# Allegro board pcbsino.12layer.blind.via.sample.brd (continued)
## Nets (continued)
VSYS_5V0: C1.2 C4.1 C6.1 C18.1 C21.1 C23.1 C25.1 C27.1 C32.1 C33.1 C37.1 C38.1 C42.1 C45.1 C46.2 C48.2 C50.2 C52.1 R4.2 R8.2(P2) R9.1 R23.1 R27.1 R44.1 R45.1 R48.2 R227.1 R228.1 R229.1 TP1.1 U1.5(SENSE) U1.6(VDD) U3.A6(LDO12_IN) U3.C4(LDO9_IN) U3.C5(LDOLN_IN) U3.C7(VCC1) U3.D11(SMPS1_IN_1) U3.D12(SMPS1_IN_2) U3.D13(SMPS1_IN_3) U3.E1(SMPS7_IN_B1_1) U3.E2(SMPS7_IN_B1_2) U3.E3(SMPS7_IN_B1_3) U3.F1(SMPS4_IN_1) U3.F2(SMPS4_IN_2) U3.F3(SMPS4_IN_3) U3.G11(SMPS2_IN_1) U3.G12(SMPS2_IN_2) U3.G13(SMPS2_IN_3) U3.H11(SMPS3_IN_1) U3.H12(SMPS3_IN_2) U3.H13(SMPS3_IN_3) U3.J1(SMPS5_IN_1) U3.J2(SMPS5_IN_2) U3.J3(SMPS5_IN_3) U3.L12(LDO34_IN) U3.L13(LDO34_IN_1) U3.M4(NC6) U3.M6(SMPS6_IN) U3.M8(SMPS9_IN) U3.M9(SMPS8_IN) U3.N3(NC7) U3.N4(NC8) U3.N6(SMPS6_IN_1) U3.N8(SMPS9_IN_1) U3.N9(SMPS8_IN_1) U4.5(VCC) XP1.10(VSYS13) XP1.28(VSYS14) XP1.46(VSYS15) XP1.64(VSYS16) XP1.78(VSYS) XP1.96(VSYS1) XP1.114(VSYS2) XP1.132(VSYS3) XP1.150(VSYS4) XP1.168(VSYS5) XP1.186(VSYS6) XP1.204(VSYS7)
VTT_DDR: C9.1 C10.1 C11.1 C66.1 C67.1 C68.1 C69.1 C70.1 C71.1 C72.1 C103.1 C104.1 C105.1 C106.1 C107.1 C108.1 C109.1 R15.1(P1) R68.1(P1) R69.1(P1) R70.1(P1) R71.1(P1) R72.1(P1) R73.1(P1) R74.1(P1) R75.1(P1) R76.1(P1) R77.1(P1) R78.1(P1) R79.1(P1) R80.1(P1) R81.1(P1) R82.1(P1) R83.1(P1) R84.1(P1) R85.1(P1) R86.1(P1) R87.1(P1) R88.1(P1) R89.1(P1) R90.1(P1) R91.1(P1) R92.1(P1) R101.1(P1) R102.1(P1) R103.1(P1) R104.1(P1) R105.1(P1) R106.1(P1) R107.1(P1) R108.1(P1) R109.1(P1) R110.1(P1) R111.1(P1) R112.1(P1) R113.1(P1) R114.1(P1) R115.1(P1) R116.1(P1) R117.1(P1) R118.1(P1) R119.1(P1) R120.1(P1) R121.1(P1) R122.1(P1) R123.1(P1) R124.1(P1) R125.1(P1) TP2.1 U2.3(VTT)
VUSB_3V3: C31.2 C160.1 C161.1 C162.1 TP17.1 U3.B9(LDOUSB_OUT) U6.AA12(VDDA33V_USB1) U6.Y12(VDDA33V_USB2)
N05979: R320.2 R321.2 XP1.200(USB1_DRVVBUS;GPIO6_12;TIMER16)
N17551517: R45.2 U3.B3(VCC_SENSE)
N17551519: R44.2 U3.A11(VCC_SENSE2)
N17551928: C17.2 U3.B7(VBG)
N25853972: R31.1 R32.1 U3.K7(BOOT1)
N28613451: R22.2 R25.2 U3.E6(NRESWARM)
N28614012: R19.2 R24.2 R26.2 U3.E5(NSLEEP)
N28708877: C15.1 U3.A2(OSC16MOUT) Y1.1
N29245750: R63.2 R64.1 U6.AE14(RTC_OSC_XI_CLKIN32)
N29975844: C16.1 U3.C1(OSC16MCAP)
N31526000: L13.1 U17.32(REGOUT)
N31599735: L19.1 U19.32(REGOUT)
N31726154: C145.1 C146.2 U12.C2(VDDIM)
N32045954: C73.1 R93.1(P1) R94.1(P1)
N32303458: C110.1 R126.1(P1) R127.1(P1)
N32341441: D2.1(REF) R5.1 R10.2 R16.2
N32341443: D2.2(CATHODE) Q1.1(BASE) R1.1 R10.1
N32341445: D3.1(REF) R6.1 R12.2 R17.2
N32341447: D3.2(CATHODE) Q2.1(BASE) R3.1 R12.1
N32350953: C319.2 U6.Y15(CAP_VDDRAM_CORE3)
N32350956: C320.1 U6.R20(CAP_VBBLDO_IVA)
N32350987: C321.2 U6.J19(CAP_VDDRAM_CORE2)
N32350990: C322.1 U6.Y14(CAP_VBBLDO_GPU)
N32351019: C323.2 U6.P19(CAP_VDDRAM_CORE4)
N32351022: C324.1 U6.J16(CAP_VBBLDO_MPU)
N32351049: C325.2 U6.Y16(CAP_VDDRAM_CORE5)
N32351052: C326.1 U6.J10(CAP_VDDRAM_DSP)
N32351083: C327.2 U6.K9(CAP_VBBLDO_DSP)
N32351086: C328.1 U6.T20(CAP_VDDRAM_IVA)
N32351113: C329.2 U6.J9(CAP_VDDRAM_DSP2)
N32351116: C330.1 U6.Y13(CAP_VDDRAM_GPU)
N32351145: C331.2 U6.K19(CAP_VDDRAM_MPU2)
N32351151: C332.1 R318.1 U6.K16(CAP_VDDRAM_MPU1)
N32351171: C333.2 U6.L9(CAP_VDDRAM_CORE1)
N32388958: R319.1 XP1.183(BACKUP_BAT)
N32392766: R230.1 R234.2 U16.7(WP)
N32392999: R164.1 R168.2 R170.2
N32637123: C35.2 U3.C8(LDOVANA_OUT)
N32670742: C14.1 R18.2 U3.A3(OSC16MIN) Y1.3
N32674796: TP4.1 U3.M11(CLK32KGO)
N32678230: R35.2 U3.B12(GPIO_0)
N32680788: R40.2 U3.C10(GPIO_5/CLK32KGO)
N32681411: R37.2 U3.A12(GPIO_2/REGEN2)
N32684937: R36.2 U3.C13(GPIO_1/VBUSDET)
N32685500: R46.1 R47.1(P1) U3.D8(VBUS)
N32689068: R41.2 R43.1 U3.G9(GPIO_7/POWERHOLD)
N32690150: R38.2 U3.H9(GPIO_3)
N32694377: R29.1 R30.1 U3.L3(BOOT0)
N32708016: TP6.1 U3.C11(RPWRON)
N32708264: TP9.1 U3.K8(PWRDOWN)
N32708462: TP10.1 U3.N12(VPROG/TESTV)
N32708995: R39.2 U3.K10(GPIO_4/SYSEN1)
N32710130: R34.1 R36.1 U4.2(A)
N32710609: R42.2 U3.N11(GPIO_6/SYSEN2)
N32734224: C34.1 R48.1 R50.2 U3.A9(LDOUSB_IN2) U3.A10(LDO7USB_IN1)
N32811364: C7.1 R8.1(P1) U1.4(CT)
N32826883: D1.2(A) R9.2
N32827036: TP7.1 U3.F8(REGEN1)
N32966375: C5.1 R2.2 R7.2 U2.1(VRI)
N32966437: R13.1 R14.1(P1) U2.7(EN)
N32966504: C13.1 R15.2(P2) U2.5(VTTS)
N32992437: R172.1 U6.A17(MCASP2_AXR7)
N33004530: R60.1 U6.AB16(WAKEUP2)
N33116208: R56.1 U6.D21(NMIN)
N33266046: Q8.D(DRAIN) R327.1 R329.1(P1)
N33266747: Q7.D(DRAIN) R323.1 R324.1(P1)
N261608581: R99.2 U6.V27(DDR1_DQS_ECC)
N261608661: R100.2 U6.V28(DDR1_DQSN_ECC)
N323928681: R160.2 U13.10(NC.10)
N323929221: R162.2 U13.8(NC.8)
N329663413: R11.2 U2.9(PGOOD)
N330092162: D4.1(C) Q3.D(DRAIN)
N330103841: D4.2(A) R23.2
N330155391: D5.2(A) R227.2
N330155500: D5.1(C) Q4.D(DRAIN)
N330160361: D6.2(A) R228.2
N330160440: D6.1(C) Q5.D(DRAIN)
N330162891: D7.2(A) R229.2
N330162970: D7.1(C) Q6.D(DRAIN)
N330247804: R161.2 U14.5(DIR)
N330247805: R163.2 U14.4(B)
N3195997380: R97.1 U9.L8(ZQ)
N3196008080: R96.1 U8.L8(ZQ)
N3196802080: R129.1 U10.L8(ZQ)
N3196813480: R130.1 U11.L8(ZQ)

Pads without a net: NOREF 1; NOREF#3 1; NOREF#5 1; NOREF#7 1; NOREF#8 1; NOREF#9 1; P1 6 17 18 19; U3 B4 C9 K4 K5 L4; U4 1; U6 A13 A16 A20 A26 A27 AA1 AA2 AB1 AB2 AC1 AC2 AD3 AD8 AD9 AD14 AE1 AE2 AE3 AE5 AE6 AE8 AE9 AF1 AF2 AF3 AF4 AF6 AF8 AF9 AG2 AG3 AG4 AG5 AG6 AG7 AG8 AH3 AH4 AH5 AH6 AH7 B22 B28 C1 C15 D1 D2 D3 E1 E2 E4 E6 E14 E15 F2 F3 F4 F5 F6 F14 G1 G14 G17 H7 K14 M3 M4 M5 N1 N2 N6 N7 N9 P1 P5 P6 P7 P9 R4 R5 R6 R9 T6 T7 T9 V23 V24 V25 V26 W19 W22 W23 Y5 Y10 Y25 Y26; U7 1; U8 J1 J9 L1 L9; U9 J1 J9 L1 L9; U10 J1 J9 L1 L9; U11 J1 J9 L1 L9; U12 A1 A2 A7 A8 A9 A10 A11 A12 A13 A14 B1 B7 B8 B9 B10 B11 B12 B13 B14 C1 C3 C5 C7 C8 C9 C10 C11 C12 C13 C14 D1 D2 D3 D4 D12 D13 D14 E1 E2 E3 E5 E8 E9 E10 E12 E13 E14 F1 F2 F3 F10 F12 F13 F14 G1 G2 G3 G10 G12 G13 G14 H1 H2 H3 H5 H12 H13 H14 J1 J2 J3 J12 J13 J14 K1 K2 K3 K6 K7 K10 K12 K13 K14 L1 L2 L3 L12 L13 L14 M1 M2 M3 M7 M8 M9 M10 M11 M12 M13 M14 N1 N3 N6 N7 N8 N9 N10 N11 N12 N13 N14 P1 P2 P7 P8 P9 P10 P11 P12 P13 P14; U17 33 38 39 40 41 42 43 44; U19 33 38 39 40 41 42 43 44; XP1 2 4 33 35 39 41 45 47 51 53 57 59 107 158 160 164 166 181 191

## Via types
v1: diameter 0.254, hole 0.102, TOP to GND_L2, 857 vias
v2: diameter 0.254, hole 0.102, GND_L2 to INT_L3, 684 vias
v3: diameter 0.457, hole 0.203, INT_L3 to SIG_L10, 312 vias
v4: diameter 0.254, hole 0.102, SIG_L10 to GND_L11, 218 vias
v5: diameter 0.254, hole 0.102, GND_L11 to BOTTOM, 597 vias
v6: diameter 0.356, hole 0.203, TOP to BOTTOM, 10 vias
v7: diameter 0.457, hole 0.203, TOP to BOTTOM, 226 vias
v8: diameter 0.406, hole 0.203, TOP to BOTTOM, 665 vias

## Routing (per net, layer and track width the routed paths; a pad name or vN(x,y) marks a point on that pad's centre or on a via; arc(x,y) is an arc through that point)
GND: length 424
  TOP w0.102: v2(21.73,2.71) 21.71,2.73 C55.2 ; C11.2 15.28,59.29 15.28,59.3 v1(15.28,59.39) ; R274.1 49.98,26.45 v2(50.26,26.45) ; v2(28.03,6.51) 28.03,6.51 28.03,6.62 U12.H10 ; v2(29.56,9.87) 29.91,9.51 30.19,9.51 30.54,9.86 U12.C4 ; C13.2 15.13,62.8 15.21,62.88 v2(15.21,62.99) ; C24.2 19.18,46.51 v1(18.46,47.23) ; C137.2 v1(17.83,18.39) ; U12.A6 v1(31.89,8.91)
  TOP w0.114: U3.G5 30.74,57.81 ; U6.W28 v8(19.07,32.77) ; U6.AD24 v8(23.07,35.97) ; U3.G4 U3.F4
  TOP w0.127: C2.2 7.62,65.79 v7(7.46,65.95) ; 53.48,27.03 54.32,26.2 54.32,23.33 53.92,22.92 50.16,22.92 49.78,23.3 ; C8.1 v7(5.71,58.2)
  TOP w0.203: U3.A7 36.38,55.42 v1(36.77,55.82) 37.05,56.1 v1(37.05,56.17) ; R191.2 44.54,25.01 v1(43.2,25.01) ; v1(30.34,35.22) 30.67,35.54 U6.AC14 30.67,35.63 v1(30.32,35.98) ; U3.L10 v1(27.25,53.32) 27.25,53.53 U3.L9 ; U6.AH20 25.84,39.57 v2(25.29,40.12) ; v1(30.19,37.61) 29.87,37.93 U6.AF15 ; U6.AE13 31.09,36.79 v1(31.06,36.79) ; U3.J6 U3.H7 ; U6.AB14 30.3,34.4 v1(30.29,34.4) 30.29,34.35 U6.AA14 30.67,33.94 v1(30.27,33.54)
  TOP w0.254: U6.T18 v8(27.87,30.37) ; v8(27.87,30.37) U6.T17 ; v8(27.87,30.37) U6.U17 v8(27.87,31.17) U6.V17 v8(27.87,31.97) ; v8(41.93,25.21) 41.88,25.16 41.08,25.16 U6.K1 ; R97.2 6.64,29.52 6.64,30.92 6.95,31.23 ; v8(3.53,8.61) 3.93,9.01 U10.T9 ; U6.A2 v8(40.67,17.57) U6.A1 v8(41.47,17.57) ; U6.J12 v8(32.67,23.97) U6.H12 v8(32.67,23.17) ; 31.48,36.37 31.48,37.17 U6.AE13 ; 31.48,36.37 U6.AD13 ; 31.48,36.37 v8(31.87,35.98) ; v8(2.68,42.35) 3.67,42.35 3.93,42.61 U8.T9 ; v2(53.48,26.53) C191.2 ; U9.D8 v8(13.93,31.81) ; U9.J8 v8(9.13,31.81) ; U11.B3 v8(14.73,25.41) ; Q5.S 39.13,4.93 v2(39.13,4.61) 39.13,3.8 38.72,3.38 C155.2 ; v2(13.12,60.08) 12.91,60.3 U2.4 ; U9.B9 v8(15.53,31.01) ; U8.G8 v8(11.53,43.01) ; U6.E19 v8(26.27,20.77) U6.D19 ; R274.1 49.69,23.39 49.78,23.3 ; U11.F9 12.13,20 v8(12.33,19.81) ; v8(31.07,27.17) U6.N14 ; 6.95,31.23 7.13,31.41 ; 6.95,31.23 v8(6.73,31.01) ; U8.A9 v8(16.33,42.21) ; v8(2.73,15.84) 3.51,15.84 3.76,15.58 3.76,15.57 U10.T1 ; C156.2 9.04,4.5 v7(8.6,4.94) ; v8(19.07,27.97) U6.P28 ; U9.P1 5.53,37.81 v8(5.13,38.21) 5.04,38.3 5.04,39.75 C98.2 ; C84.1 13.38,49.66 v8(13.13,49.41) ; U8.G9 v8(11.53,42.21) ; C82.1 5.04,41.08 5.04,42.12 v8(5.13,42.21) 5.53,42.61 U8.P9 ; U5.3 22.08,6.9 v2(22.71,6.27) ; U3.M13 26.74,50.63 v7(26.36,51.02) 26.74,51.4 U3.M12 ; U6.R1 v1(41.98,29.17) ; v7(25.45,59.75) 25.78,59.42 U3.N2 25.95,59.42 v7(26.33,59.04) ; C125.1 6.98,27.6 v8(7,27.57) 7,26.73 U11.M1 ; U6.AE19 v8(26.27,36.77) U6.AD19 ; v7(26.33,59.83) 26.73,60.22 U3.M1 ; v7(26.33,59.83) U3.N1 ; v7(26.33,59.83) 26.74,59.42 U3.M2 ; U11.G1 v8(11.53,27.01) ; v7(27.93,54.24) 27.55,54.62 U3.L8 ; U3.D5 U3.D4 U3.E4 ; U11.J2 v8(9.13,26.21) ; v1(35.07,33.52) 35.07,33.57 U6.AA9 ; U10.E8 v8(13.13,9.41) ; v1(33.47,34.37) U6.AB11 32.68,35.16 v1(32.68,35.17) ; v1(33.47,34.37) U6.AA10 v8(34.27,34.37) U6.AA9 ; v1(33.47,34.37) U6.AA11 32.71,34.33 v1(32.68,34.33) ; R129.2 9.34,7.25 v7(9.64,6.95) ; U6.AH28 19.31,39.57 19.26,39.63 18.62,39.63 v8(18.57,39.68) ; U9.B1 15.13,37.81 v8(15.53,38.21) ; U11.B9 15.13,19.95 14.9,19.72 14.9,19.71 v8(14.89,19.69) 14.93,19.69 14.94,19.68 15.62,19.68 15.93,19.99 U11.A9 ; v7(35.96,60.59) 35.59,60.22 U3.A1 ; v2(55.76,27.15) 55.23,26.63 R272.1 ; R287.1 46.27,35.21 46.52,34.96 v1(46.52,34.94) ; v8(41.62,18.8) 41.58,18.8 41.56,18.77 U6.B1 ; v8(9.13,37.41) U9.J2 ; C121.1 7.13,16.94 v1(7.13,16.47) U10.M1 ; v7(32.02,53.43) 32.02,53.3 32.3,53.02 U3.E10 ; v7(32.02,53.43) 32.02,53.45 32.34,53.77 U3.E9 ; v7(32.02,53.43) 31.62,53.02 U3.F10 U3.G10 U3.F9 31.63,53.82 v7(32.02,53.43) ; U11.J8 v8(9.93,21.41) ; U3.C3 33.94,58.62 v7(34.33,59.02) 33.94,59.41 U3.C2 ; v7(36.46,58.23) 36.06,57.82 U3.A4 ; U9.M1 6.7,38.24 6.7,39.6 C89.1 ; v8(41.65,32.63) 41.47,32.63 41.22,32.37 U6.W1 ; v8(26.27,26.37) U6.M19 v1(26.27,27.17) U6.N19 ; U3.H7 29.94,55.46 v7(30.29,55.82) ; U6.T11 v8(32.67,29.57) ; U6.T11 v8(32.67,30.37) U6.T12 ; U6.T11 v8(33.47,30.37) U6.T10 ; v8(32.67,29.57) U6.R12 v8(31.87,29.57) ; v8(32.67,29.57) U6.T12 ; U11.P9 5.53,19.84 5.15,19.45 v8(5.15,19.37) 5.15,18.58 5.22,18.5 C128.1 ; U8.P1 5.53,49.01 5.53,49.75 v8(5.5,49.77) 5.26,50.01 C93.2 ; U6.R21 v1(24.67,29.57) U6.T21 v1(24.67,30.37) U6.U21 ; U6.K15 v8(29.47,24.77) U6.J15 v8(29.47,23.97) ; v8(41.9,21.97) U6.F1 ; U3.G4 30.74,57.81 v7(31.16,57.39) ; v7(32.61,55) 32.61,55.16 U3.E7 ; v7(32.61,55) 32.34,54.74 U3.E8 32.33,54.62 v7(31.92,55.03) 31.54,55.41 U3.F7 ; v7(32.61,55) 33.03,55.42 U3.D7 ; v6(34.24,36.79) 34.24,36.72 34.22,36.71 ; v8(24.67,31.17) U6.U21 ; U6.U21 v8(25.47,31.17) U6.U20 ; v8(19.43,17.41) 19.43,17.94 U6.A28 ; v8(29.47,27.17) U6.N15 ; U6.AB14 v1(31.07,34.37) U6.AA14 ; v7(31.94,55.84) 31.56,56.22 U3.F6 ; v8(11.53,38.21) 11.13,37.81 U9.G1 ; v8(2.58,19.83) 3.55,19.83 U11.T9 ; v8(31.86,21.57) U6.E13 ; v2(21.38,25.01) 21.71,25.01 21.87,25.17 ; v2(48.33,10.27) 48.33,9.75 C207.2 48.33,9.72 47.92,9.31 47.92,5.96 48.15,5.73 52.31,5.73 52.57,5.98 52.57,8.7 R301.1 52.53,8.84 v2(51.6,9.77) ; v1(46.17,36.03) 46.05,36.15 R278.1 R280.1 ; U6.AH1 40.68,39.18 v1(40.66,39.18) ; U6.AH1 v8(40.67,39.97) U6.AH2 ; U6.AH1 v8(41.47,39.17) U6.AG1 ; U6.AH1 41.13,39.57 v1(41.55,39.99) ; U12.P6 v2(24.66,8.75) ; U3.L5 27.54,57.02 v7(27.93,56.63) 27.54,56.24 U3.L6 27.55,56.22 v7(27.93,55.84) 27.54,55.45 U3.L7 ; U9.E2 12.73,37.01 v8(13.13,37.41) ; R239.1 43.69,5.18 Q6.S v2(43.71,4.69) ; v7(30.29,55.82) 29.94,56.17 U3.H6 ; v7(30.29,55.82) 30.69,55.42 U3.G7 v7(31.13,55.82) ; U9.B3 v8(15.56,35.78) ; C129.2 7.05,8.29 v8(6.73,8.61) 7.13,9.01 U10.M9 ; U3.G5 30.79,57.02 v7(31.16,57.39) ; C273.2 10.54,16.64 v8(11.32,15.86) 11.32,15.6 U10.G1 ; U10.G8 v8(11.53,9.41) ; v8(36.67,21.57) U6.F7 ; U6.F7 v8(35.87,22.37) ; U6.F7 v8(36.67,22.37) U6.G7 v8(35.87,22.37) ; U6.AA20 v8(25.47,34.37) U6.AB20 v8(25.47,35.17) ; v7(31.16,57.39) 31.54,57.77 U3.F4 ; v7(31.16,57.39) 31.17,57.39 U3.F5 ; U6.R15 v8(29.47,29.57) U6.T15 v8(29.47,30.37) U6.U15 v8(29.47,31.17) U6.V15 v8(29.47,31.97) U6.W15 ; U6.AE10 33.87,37.13 34.22,36.77 34.22,36.71 ; v8(23.39,17.16) 23.39,17.89 U6.A23 ; U6.AA8 35.88,33.57 v1(35.88,33.57) ; U6.AA8 v1(35.07,34.37) U6.AA9 ; U6.AA8 35.86,34.36 v1(35.86,34.38) ; U6.K24 22.67,25.15 v2(22.27,24.75) 21.87,25.15 21.87,25.17 ; U11.D8 13.33,20.81 v8(13.13,20.61) 12.93,20.8 U11.E8 ; U11.B1 15.37,26.85 15.37,26.85 v8(15.53,27.01) ; U10.P9 5.53,9.01 v8(5.13,8.61) 5.04,8.52 5.04,7.45 C122.1 ; v8(35.87,22.37) U6.G8 v8(35.07,22.37) U6.G9 ; C90.1 5.04,29.72 5.04,30.92 5.38,31.26 ; U6.T12 v8(31.87,29.57) ; U11.E1 12.93,26.81 12.93,26.81 v8(13.13,27.01) ; v1(9.13,43.01) 9.53,43.41 U8.J8 9.9,43.78 v1(9.9,43.83) ; v1(47.03,35.95) 46.97,36.02 R281.1 ; v7(33.57,51.8) 33.94,51.44 U3.C12 ; v8(31.87,29.57) U6.R13 ; U8.T1 3.93,49.01 3.7,49.24 v8(3.37,49.24) ; U11.M9 6.78,19.86 v8(6.78,19.37) 6.78,18.65 C124.1 ; U6.L14 v8(31.07,25.57) U6.L13 ; 3.93,31.41 v8(3.53,31.01) ; U6.K5 v8(38.27,24.77) U6.K4 v8(39.07,24.77) ; U3.B10 34.75,53.02 v7(35.14,52.64) 34.74,52.24 U3.B11 ; R303.1 46.53,8.46 v2(46.45,8.55) 46.42,8.52 46.34,8.52 R302.1 ; 34.22,36.71 33.89,36.37 U6.AD10 ; v8(15.14,16.13) 15.21,16.07 15.21,15.48 U10.B1 ; U10.B9 v8(15.53,8.61) ; v2(24.59,9.73) 24.63,9.73 24.82,9.91 U12.P4 ; U8.B3 v8(15.53,47.81) ; U10.J8 9.53,9.8 v8(9.93,9.41) ; C85.1 15.13,49.81 v8(15.53,49.41) ; v8(7.1,50.05) 7.13,50.03 7.13,49.01 U8.M1 ; U3.H10 U3.J10 U3.J9 ; v8(11.53,20.61) 11.33,20.8 U11.G8 ; v8(19.07,23.94) 19.07,23.97 U6.J28 ; v8(2.1,38.44) 3.29,38.44 3.93,37.81 U9.T1 ; U10.J2 v8(9.13,15.01) ; U10.D8 v8(13.93,9.41) ; U6.A6 37.1,17.95 v8(37.1,17.42) ; v8(11.53,31.81) U9.G8 ; U10.G9 v8(11.53,8.61) ; v1(29.47,34.37) U6.AA15 ; R237.1 41.67,5.34 Q4.S v2(41.45,4.59) ; v2(50.66,27.67) 50.63,27.64 C188.2 50.63,26.21 50.95,25.89 Y4.2 ; v8(30.93,16.89) 30.93,16.93 30.67,17.19 U6.A14 ; U3.A13 35.98,50.18 v7(36.31,50.18) ; v7(28.71,58.24) 28.68,58.24 28.34,58.59 U3.K3 ; U9.F9 v8(12.33,31.01) ; U11.D1 13.73,26.81 13.73,26.81 v8(13.93,27.01) ; v8(41.47,36.77) U6.AD1 ; U9.E8 v8(13.13,31.81) ; U8.J2 v8(9.13,48.61) ; 21.87,25.17 U6.K25 ; C133.2 5.04,17.04 5.04,15.89 5.13,15.81 v8(5.13,15.8) 5.14,15.8 U10.P1 ; v7(21.99,63.82) 22.75,63.06 v3(23.73,63.06) 23.73,62.12 v7(24.25,61.61) ; U10.D1 13.48,15.46 13.48,16.04 13.24,16.28 12.73,16.28 ; U10.B3 15,13.68 15,13.09 v8(14.95,13.04) ; v7(35.12,59.81) U3.B2 ; U11.G9 11.33,20.01 v8(11.53,19.81) ; U6.AH8 36.45,40.56 37.32,40.56 v8(37.32,40.55) ; U3.H5 U3.H4 U3.J4 ; U11.T1 3.83,26.71 3.12,26.71 v8(3.01,26.61) ; U8.E8 v8(13.13,43.01) ; U9.D1 13.53,37.89 v7(13.17,38.24) 12.74,37.81 U9.E1 ; U6.N24 v8(22.27,27.17) U6.N25 ; 5.38,31.26 v8(5.13,31.01) ; 5.38,31.26 5.53,31.41 ; v8(21.47,32.77) U6.W25 v8(22.27,32.77) U6.W24 ; 12.73,16.28 U10.E1 ; 12.73,16.28 v8(12.16,16.85) ; U8.F9 v8(12.33,42.21) ; v7(33.55,55.82) U3.D6 ; U10.F9 v8(12.33,8.61) ; v7(33.47,53.35) U3.D10 ; U6.U14 v8(31.07,30.37) U6.T14 ; U6.D13 v8(31.86,20.77) ; U8.E2 v8(13.13,48.61) ; U8.M9 7.13,42.1 v8(6.8,41.77) 6.8,41.15 C94.2 ; C134.2 5.02,28.14 5.02,28.03 4.92,27.94 v8(4.92,27.32) 5.53,26.71 U11.P1 ; U9.G9 v8(11.53,31.01) ; U10.A9 v8(16.33,8.61)
  TOP w0.381: C81.1 7.13,50.85 7.13,50.08 v8(7.1,50.05) ; v7(27.93,54.24) 27.93,54.22 U3.L9 ; U10.E2 v8(12.33,15.01) ; U2.8 v7(12.41,64.51) ; XP1.71 56.91,23.18 v7(56.46,23.64) ; XP1.1 v7(56.97,2.18) ; 7.13,31.41 U9.M9 ; C54.2 v2(16.83,6.79) ; U9.A9 v8(15.53,31.01) ; C12.2 14.77,66.19 14.77,66.76 v7(14.72,66.82) ; R130.2 6.95,18.48 C124.1 ; v2(24.66,49.82) 24.39,50.08 R42.1 ; v2(48.43,19.47) 48.24,19.28 C214.2 ; C234.2 C237.2 16.35,66.43 v7(15.84,66.94) ; U9.T9 3.93,31.41 ; v2(56.74,13.25) 57,12.98 XP1.37 ; C127.1 13.56,27.37 v8(13.93,27.01) ; U8.B9 v8(15.13,41.82) ; U11.D1 13.53,26.61 U11.E2 ; U8.D8 v8(13.13,43.01) ; v8(13.13,49.41) U8.E1 ; C76.2 11.72,49.6 v8(11.53,49.41) 11.13,49.01 U8.G1 ; v1(36.59,6.69) 36.59,6.7 v1(36.59,7.38) ; C101.2 15.47,38.27 v8(15.53,38.21) ; U3.N13 25.92,50.61 25.85,50.61 v7(25.42,50.18) ; U9.P9 5.53,31.41 ; U8.B1 v8(15.53,49.41) ; v8(13.13,48.61) 13.53,49.01 U8.D1
  GND_L2 w0.091: 27.87,17.27 27.93,17.11 ; 29.5,18.49 29.5,18.01 ; 44.33,9.36 43.81,9.36
  GND_L2 w0.102: v1(7.13,16.47) 6.72,16.47
  SIG_L10 w0.127: v5(36.24,39.89) 35.93,39.89 35.45,39.41 33.18,39.41 32.28,38.5 32.28,35.78 32.1,35.6 30.93,35.6 30.88,35.55 29.65,35.55 29.63,35.57 29.32,35.57 29.07,35.81 29.07,36.15 29.28,36.36 29.3,36.36 29.31,36.37 30.43,36.37 31.46,37.4 31.46,38.9 33.04,40.48 v5(33.77,40.48)
  GND_L11 w0.091: 11.75,57.75 11.75,57.37 ; 2.66,43.17 2.66,43.55
  BOTTOM w0.102: v5(50.23,10.88) 50.28,10.83 C212.2 ; C198.2 53.12,10.41 v5(53.13,10.4)
  BOTTOM w0.114: v5(30.67,39.89) 30.27,39.48 30.27,36.92 29.72,36.37 29.18,36.37 29.07,36.48 29.07,36.94 28.69,37.31 28.69,39.23 27.91,40.01 C57.2 ; C320.2 23.08,28.99 v5(23.05,29.02) ; v5(36.24,39.89) 36.42,39.89 36.61,40.09 C60.2 ; R208.2 40.13,25.04 40.1,25.01 v5(40.05,25.01) ; v5(39.42,23.64) 39.51,23.54 39.51,23.53 39.65,23.4 C315.2 ; v8(19.07,32.77) 19.07,32.77 C275.2
  BOTTOM w0.203: R62.2 33.71,40.54 33.09,41.16 33.09,44.18 33.24,44.34 37.05,44.34 37.23,44.16 37.23,41.07 C60.2 ; C57.2 27,40.42 26.69,40.73 26.69,43.88 27.09,44.29 30.7,44.29 31.03,43.96 31.03,40.44 C58.2 31,40.21 v5(30.67,39.89)
  BOTTOM w0.254: C251.2 34.99,32.09 C248.2 ; R131.2 9.15,6.95 v7(9.64,6.95) ; C225.2 29.47,29.68 v8(29.47,29.57) ; v8(11.53,8.61) 11.41,8.49 11.41,8.14 C118.1 ; v8(29.47,24.77) 29.31,24.93 C256.2 ; C304.2 C247.2 ; C314.2 30.49,23.27 C324.2 29.88,23.57 v8(29.47,23.97) ; C86.2 v8(15.13,41.82) ; v7(35.96,60.59) 36.92,61.56 37.9,61.56 C15.2 ; C136.2 15.02,19.5 14.95,19.57 14.95,19.63 v8(14.89,19.69) ; v8(29.47,23.97) 29.47,23.94 29.5,23.91 ; v8(29.47,23.97) 29.26,24.19 C293.2 ; C307.2 41.62,32.65 v8(41.65,32.63) ; v8(16.33,42.21) 16.18,42.36 C95.2 ; v7(38.19,62.17) 38.35,62.32 42.74,62.32 43.27,61.79 v5(43.27,60.03) 43.27,57.98 43.12,57.82 42.54,57.82 42.54,57.82 40.43,57.82 40.42,57.82 38.73,57.82 C14.2 36.85,58.61 v7(36.46,58.23) ; v5(25.39,20.36) 25.85,20.36 v8(26.27,20.77) ; C277.2 29.22,31.72 v8(29.47,31.97) ; v8(14.95,13.04) 15.16,13.25 C120.1 ; C114.2 7.03,8.3 v8(6.73,8.61) ; C159.2 35.22,0.67 v7(35.2,0.65) ; v7(15.71,7.43) 15.71,7.13 16.04,6.79 C117.2 ; v8(29.47,31.17) 29.47,30.96 C229.2 29.47,30.49 v8(29.47,30.37) ; C109.2 3.01,8.09 v8(3.53,8.61) ; v8(11.53,9.41) 11.59,9.47 C132.2 ; C138.2 11.67,19.67 v8(11.53,19.81) ; C323.1 26.28,26.39 v8(26.27,26.37) ; C97.2 14.91,31.52 15.43,31.01 v8(15.53,31.01) ; C87.1 15.54,35.76 v8(15.56,35.78) ; C130.2 15.71,8.43 v8(15.53,8.61) ; 32.18,23.57 32.27,23.57 v8(32.67,23.17) ; C332.2 31.49,21.93 v8(31.86,21.57) 31.51,21.21 R318.2 31.53,21.1 v8(31.86,20.77) ; v8(15.14,16.13) 15.38,16.36 C119.1 ; v8(29.47,27.17) 29.32,27.32 C263.2 ; C116.2 7.04,19.47 6.89,19.47 v8(6.78,19.37) ; v8(18.57,39.68) 18.81,39.92 19.52,39.92 C282.2 ; v8(9.01,15.91) 9.19,16.09 C107.2 ; R29.2 28.67,58.2 v7(28.71,58.24) ; C88.1 13.56,38.63 v7(13.17,38.24) ; 7.93,41.4 8.67,41.4 v5(9.08,41.82) 9.09,41.83 C131.2 ; C108.2 4.86,19.08 v8(5.15,19.37) ; 23.71,62.14 v7(24.25,61.61) ; C259.2 30.78,25.29 v8(31.07,25.57) ; C18.2 v7(36.31,50.18)
  BOTTOM w0.381: C71.2 10.25,35.95 10.57,35.63 10.57,35.38 10.91,35.04 10.94,35.04 10.99,34.99 ; C69.2 7.93,41.4 C77.2 7.19,42.02 v8(6.8,41.77) ; C99.2 9.28,38.05 v8(9.13,38.21) ; v8(41.9,21.97) 41,21.07 C316.2 ; v8(15.53,31.01) 15.68,30.86 C100.2 ; v8(7.1,50.05) 7.24,49.92 C92.2 ; v7(1.11,14.08) 1.21,13.98 1.21,12.81 0.4,12 MH6.1 ; C35.1 35.07,52.57 v7(35.14,52.64) ; 10.99,34.99 C269.2 ; 10.99,34.99 11.85,34.99 12.34,35.47 v8(12.34,35.57) 12.34,36.23 C271.2 ; v7(19.24,2.12) 19.73,2.61 U7.3 ; v7(32.61,55) 32.65,55.05 C53.2 ; v8(2.73,15.84) 2.69,15.89 2.69,17.11 2.96,17.38 R128.2 ; C328.2 24.56,31.07 v8(24.67,31.17) ; v7(14.72,66.82) 15.49,66.05 C240.2 15.84,66.33 v7(15.84,66.94) ; C78.2 v8(6.73,31.01) 6.75,30.99 C70.2 ; v8(11.07,13.22) 10.62,13.67 C106.2 ; v8(11.53,38.21) 11.62,38.3 C79.2 ; v8(13.13,27.01) 13.56,27.44 C126.1 ; R95.2 2.93,39.91 2.35,39.33 2.35,38.69 v8(2.1,38.44) ; v8(11.53,31.01) 11.74,30.79 C91.1 ; R98.2 8.78,29.27 7.08,27.57 v8(7,27.57) 7.14,27.44 C135.2 ; v8(11.32,15.86) 11.49,16.03 C113.2 ; v7(34.33,59.02) 34.36,58.99 C50.1 35.12,59.78 v7(35.12,59.81) ; C231.2 20.03,66.45 C235.2 19.51,66.97 v7(19.36,66.97) ; v8(11.53,27.01) 11.72,27.2 C115.2
  vias: v1(6.77,17.31) v1(8.58,61.99) v1(8.83,64.61) v1(8.78,63.56) v1(9.29,61.96) v1(9.97,62.93) v1(9.97,61.63) v1(10.84,62.93) v1(10.81,61.63) v1(13.83,61.63) v1(13.91,62.85) v1(14.55,62.88) v1(14.55,62.34) v1(14.95,55.39) v1(14.93,54.52) v1(15,57.67) v1(14.98,54.93) v1(15.36,55.39) v1(15.28,54.93) v1(15.36,54.55) v1(15.66,57.67) v1(15.84,55.39) v1(15.84,54.93) v1(15.84,54.55) v1(15.92,61.79) v1(15.94,59.53) v1(16.02,61.05) v1(15.99,60.29) v1(16.63,61.1) v1(16.6,59.98) v1(16.73,60.59) v1(16.98,3.49) v1(18.51,9.03) v1(19.09,45.35) v1(19.27,47.64) v1(20.21,45.35) v1(20.18,6.9) v1(20.31,47.61) v1(22.17,4.97) v1(22.9,9.44) v1(24.55,3.32) v1(25.52,12.38) v1(25.54,10.91) v1(25.54,9.41) v1(26.59,6.41) v1(27.04,7.91) v1(27.45,9.92) v1(27.55,53.86) v1(27.53,9.41) v1(27.6,8.7) v1(28.13,7.76) v1(28.31,12.31) v1(28.52,9.94) v1(28.54,9.41) v1(28.82,56.55) v1(28.77,54.17) v1(28.77,53.45) v1(28.8,8.4) v1(28.8,7.51) v1(29.46,54.14) v1(29.53,57.82) v1(29.56,56.63) v1(29.51,55.84) v1(29.53,53.4) v1(29.54,8.41) v1(29.94,6.44) v1(30.12,7.61) v1(30.32,57.44) v1(30.29,56.71) v1(30.85,12.05) v1(31.13,55.11) v1(31.16,53.45) v1(31.18,54.17) v1(31.77,56.59) v1(31.92,58) v1(31.94,54.22) v1(32.66,54.06) v1(32.76,58.1) v1(32.83,56.58) v1(32.83,55.74) v1(32.83,3.82) v1(33.06,8.52) v1(33.14,57.42) v1(33.19,6.92) v1(33.42,55.16) v1(34.74,54.62) v1(35.91,40.04) v1(36.24,8.57) v1(37.76,49.39) v1(38.73,52.21) v1(38.85,49.39) v1(38.9,55.92) v1(39.16,5.86) v1(39.87,57.57) v1(39.92,54.55) v1(39.92,53.48) v1(40.68,57.16) v1(40.94,54.27) v1(41.55,29.17) v1(41.57,49.87) v1(41.57,47.66) v1(41.57,45.5) v1(41.67,46.5) v1(42.16,47.64) v1(42.21,45.48) v1(42.59,49.49) v1(42.69,46.44) v1(43.22,23.55) v1(43.37,49.49) v1(44.21,12.81) v1(44.57,65.27) v1(45.15,53.96) v1(45.13,27.74) v1(45.25,9.46) v1(45.39,16.31) v1(45.39,15.41) v1(45.58,65.14) v1(45.61,63.16) v1(45.64,32.4) v1(45.94,19.28) v1(46.04,31.61) v1(46.17,53.91) v1(46.15,24.57) v1(46.15,23.71) v1(46.15,22.87) v1(46.15,22.09) v1(46.15,21.22) v1(46.25,32.42) v1(46.18,20.1) v1(46.8,26.78) v1(47.06,19.28) v1(47.46,56.45) v1(47.67,14.47) v1(47.72,15.05) v1(47.79,12.13) v1(47.92,36.23) v1(47.9,12.87) v1(48.02,26.07) v1(48.48,8.8) v1(48.66,26.07) v1(48.66,12.1) v1(48.71,13.68) v1(48.79,12.89) v1(49.29,12.15) v1(49.47,55.31) v1(49.55,14.52) v1(49.52,13.75) v1(49.5,12.97) v1(49.62,51.83) v1(50.11,12.18) v1(50.23,14.52) v1(50.23,13.75) v1(50.23,13.04) v1(50.36,31.79) v1(50.33,31.28) v1(50.46,58.79) v1(50.44,30.75) v1(50.56,57.44) v1(50.49,55.13) v1(50.49,30.14) v1(50.54,29.55) v1(50.56,15) v1(50.63,25.82) v1(50.59,19.06) v1(50.69,56.15) v1(50.74,40.68) v1(50.82,14.54) v1(50.87,13.75) v1(50.87,13.02) v1(50.94,12.18) v1(51.07,30.75) v1(51.1,30.14) v1(51.12,29.55) v1(51.17,31.23) v1(51.35,15.15) v1(51.38,40.7) v1(51.6,60.01) v1(51.76,61.15) v1(51.76,58.81) v1(51.68,57.47) v1(51.76,55.13) v1(51.71,6.44) v1(51.86,31.26) v1(51.83,30.75) v1(51.81,29.55) v1(51.93,33.39) v1(51.96,33.01) v1(51.96,32.42) v1(51.88,30.11) v1(52.04,31.86) v1(52.06,18.89) v1(52.62,52.39) v1(52.57,4.43) v1(52.75,5.32) v1(52.85,8.93) v1(53.13,3.67) v1(53.57,23.64) v1(53.71,3.8) v1(53.99,5.5) v1(54.98,6.95) v1(55.06,5.04) v1(55.49,32.35) v1(55.74,9.64) v1(55.82,8.85) v1(55.82,7.79) v1(55.92,18.5) v1(56.05,33.08) v1(56.05,32.17) v1(56,21.83) v1(55.97,21.15) v1(56,19.37) v1(56.15,29.05) v1(56.3,30.65) v1(56.28,27.78) v1(56.56,20.13) v1(56.63,9.77) v1(56.81,30.44) v1(56.81,10.91) v1(56.94,27.09) v1(56.96,7.79) v1(57.52,35.78) v1(57.55,30.37) v1(57.62,62.78) v1(57.57,57.39) v1(57.57,51.98) v1(57.57,46.6) v1(57.62,18.38) v1(57.57,12.97) v1(57.7,23.2) v1(57.68,2.2) v1(58.03,62.78) v1(58.03,57.39) v1(58.11,51.98) v1(58.11,41.16) v1(58.11,35.78) v1(58.16,30.37) v1(58.21,46.6) v1(58.26,23.2) v1(58.26,18.35) v1(58.23,12.99) v1(59.22,41.19) v1(59.35,7.58) v2(14.95,55.39) v2(14.93,54.52) v2(14.98,54.93) v2(15.36,55.39) v2(15.28,54.93) v2(15.36,54.55) v2(15.84,55.39) v2(15.84,54.93) v2(15.84,54.55) v2(16.98,3.49) v2(18.51,9.03) v2(27.53,9.41) v2(36.24,8.57) v2(39.16,5.86) v2(41.57,49.87) v2(41.57,47.66) v2(41.57,45.5) v2(41.67,46.5) v2(42.16,47.64) v2(42.21,45.48) v2(42.59,49.49) v2(42.69,46.44) v2(43.37,49.49) v2(44.21,12.81) v2(45.25,9.46) v2(46.04,31.61) v2(46.8,26.78) v2(47.67,14.47) v2(47.72,15.05) v2(47.79,12.13) v2(47.9,12.87) v2(48.02,26.07) v2(48.48,8.8) v2(48.66,26.07) v2(48.66,12.1) v2(48.71,13.68) v2(48.79,12.89) v2(49.29,12.15) v2(49.47,55.31) v2(49.55,14.52) v2(49.52,13.75) v2(49.5,12.97) v2(50.11,12.18) v2(50.23,14.52) v2(50.23,13.75) v2(50.23,13.04) v2(50.36,31.79) v2(50.33,31.28) v2(50.44,30.75) v2(50.49,30.14) v2(50.54,29.55) v2(50.56,25.84) v2(50.56,15) v2(50.59,19.06) v2(50.74,40.68) v2(50.82,14.54) v2(50.87,13.75) v2(50.87,13.02) v2(50.94,12.18) v2(51.07,30.75) v2(51.1,30.14) v2(51.12,29.55) v2(51.17,31.23) v2(51.35,15.15) v2(51.38,40.7) v2(51.71,6.44) v2(51.86,31.26) v2(51.83,30.75) v2(51.81,29.55) v2(51.93,33.39) v2(51.96,33.01) v2(51.96,32.42) v2(51.88,30.11) v2(52.04,31.86) v2(52.06,18.89) v2(52.85,8.93) v2(53.51,23.66) v2(56,21.83) v2(55.97,21.15) v2(56.15,29.05) v2(56.3,30.65) v2(56.28,27.78) v2(56.81,30.44) v2(56.96,7.79) v2(57.52,35.78) v2(57.55,30.37) v2(57.62,62.78) v2(57.57,57.39) v2(57.57,51.98) v2(57.57,46.6) v2(57.62,18.38) v2(57.57,12.97) v2(57.7,23.2) v2(57.68,2.2) v2(58.03,62.78) v2(58.03,57.39) v2(58.11,51.98) v2(58.11,41.16) v2(58.11,35.78) v2(58.16,30.37) v2(58.21,46.6) v2(58.26,23.2) v2(58.26,18.35) v2(58.23,12.99) v2(59.22,41.19) v2(59.35,7.58) v3(21.05,60.13) v3(21.23,8.34) v3(21.73,53.15) v3(21.81,57.14) v3(25.01,62.83) v3(28.92,3.95) v3(30.95,45.38) v3(41.52,49.26) v3(44.54,46.37) v3(49.12,45.33) v3(53.05,56.12) v3(56.94,47) v3(56.91,45.73) v5(0.7,0.8) v5(2.61,33.17) v5(13.38,52.49) v5(13.91,51.47) v5(14.47,53.2) v5(14.65,50.76) v5(15.03,52.31) v5(15.28,55.77) v5(15.59,51.45) v5(16.22,60.16) v5(16.37,61.02) v5(17.01,60.11) v5(17.04,50.48) v5(17.57,61.4) v5(17.64,61.84) v5(17.7,60.74) v5(17.67,60.08) v5(17.67,34.33) v5(18.41,60.03) v5(18.51,50.66) v5(18.74,54.67) v5(18.74,49.57) v5(18.69,46.9) v5(18.69,44.56) v5(18.69,40.83) v5(18.79,55.66) v5(18.81,41.97) v5(18.94,45.2) v5(19.07,34.1) v5(19.17,8.29) v5(19.22,44.59) v5(19.35,59.98) v5(19.47,35.09) v5(19.93,47.03) v5(19.91,22.47) v5(20.11,60.62) v5(20.16,35.34) v5(20.21,59.98) v5(20.46,55.26) v5(20.39,38.91) v5(20.64,49.57) v5(20.67,32.88) v5(20.62,30.47) v5(20.62,21.35) v5(20.77,50.56) v5(20.95,11.54) v5(21.02,61.02) v5(21,40.55) v5(21.07,61.71) v5(21.15,24.73) v5(21.15,12.61) v5(21.15,10.3) v5(21.12,9.21) v5(21.25,47.1) v5(21.23,42.28) v5(21.35,21.45) v5(21.63,40.83) v5(21.76,41.59) v5(21.91,42.79) v5(22.06,62.88) v5(22.06,62.12) v5(21.99,54.6) v5(22.06,53.53) v5(22.01,47.08) v5(22.12,56.71) v5(22.12,55.69) v5(22.09,51.02) v5(22.12,46.24) v5(22.14,9.39) v5(22.27,59.07) v5(22.24,58.33) v5(22.27,57.47) v5(22.19,45.48) v5(22.24,44.67) v5(22.22,43.27) v5(22.19,41.01) v5(22.24,10.2) v5(22.29,52.51) v5(22.29,43.88) v5(22.5,42.33) v5(22.52,12.81) v5(22.75,10.76) v5(22.7,8.73) v5(22.8,44.59) v5(22.83,12.08) v5(22.85,9.72) v5(22.88,63.82) v5(22.93,60.03) v5(22.9,58.71) v5(22.98,55.08) v5(23.03,53.3) v5(23.03,51.37) v5(23.06,26.33) v5(23,22.47) v5(23.08,57.16) v5(23.18,56.15) v5(23.23,2.78) v5(23.28,0.75) v5(23.46,4.28) v5(23.61,63.79) v5(23.72,62.24) v5(23.84,24.07) v5(23.84,16.47) v5(23.89,12.89) v5(24.15,44.59) v5(24.43,63.79) v5(24.58,22.09) v5(24.78,45.12) v5(24.86,44.77) v5(24.99,12.89) v5(25.26,40.2) v5(25.19,25.46) v5(25.44,44.51) v5(25.67,29.22) v5(25.67,5.19) v5(26.13,60.85) v5(26.08,32.8) v5(26.08,32.07) v5(26.2,25.89) v5(26.33,30.29) v5(26.31,11.34) v5(26.43,12.66) v5(26.51,45.02) v5(26.51,44.49) v5(26.48,28.46) v5(26.51,24.22) v5(26.64,48.22) v5(26.81,24.78) v5(27.09,47.56) v5(27.29,38.88) v5(27.37,29.45) v5(27.55,35.04) v5(27.6,48.35) v5(27.65,46.83) v5(27.75,45.05) v5(27.73,5.17) v5(27.78,45.96) v5(27.91,12.66) v5(27.98,41.59) v5(28.08,47.79) v5(28.08,39.84) v5(28.1,22.49) v5(28.36,10.83) v5(28.52,48.83) v5(28.52,46.9) v5(28.49,5.22) v5(28.64,45.05) v5(28.59,36.21) v5(28.74,53.58) v5(28.85,47.89) v5(28.82,45.94) v5(29.02,34.35) v5(28.97,18.38) v5(29.02,11.47) v5(29.3,7.94) v5(29.46,52.59) v5(29.46,51.73) v5(29.4,6.97) v5(29.51,45.91) v5(29.48,3.8) v5(29.58,47.54) v5(29.66,46.83) v5(29.58,34.35) v5(29.61,6.11) v5(29.71,48.81) v5(29.74,12.66) v5(30.01,36.26) v5(30.19,49.11) v5(30.34,27.65) v5(30.4,43.68) v5(30.37,34.38) v5(30.52,30.98) v5(30.57,48.88) v5(30.57,45.1) v5(30.57,26.18) v5(30.8,29.68) v5(30.88,49.26) v5(30.93,11.37) v5(31.03,17.64) v5(31.16,49.67) v5(31.16,34.38) v5(31.08,9.39) v5(31.36,45.73) v5(31.34,45.1) v5(31.28,26.43) v5(31.51,17.06) v5(32.07,50.15) v5(32.12,17.16) v5(32.17,33.39) v5(32.33,13.32) v5(32.48,64.43) v5(32.48,42.53) v5(32.61,6.21) v5(32.76,35.19) v5(32.76,32.86) v5(32.91,15.43) v5(32.91,14.8) v5(33.06,40.55) v5(33.32,17.79) v5(33.47,27.29) v5(33.55,42.08) v5(33.62,6.19) v5(33.7,23.69) v5(33.93,14.92) v5(34.08,27.24) v5(34.28,28.18) v5(34.66,15.48) v5(34.71,14.77) v5(34.87,33.06) v5(34.87,17.74) v5(34.87,16.93) v5(34.79,16.19) v5(34.97,63.59) v5(34.92,24.75) v5(34.99,35.67) v5(34.99,26.1) v5(35.12,25.57) v5(35.3,36.31) v5(35.27,6.21) v5(35.65,33.95) v5(35.7,28.97) v5(35.83,35.65) v5(35.96,39.33) v5(35.91,36.26) v5(35.96,16.04) v5(36.01,37.38) v5(35.99,18.3) v5(36.06,14.8) v5(36.47,38.65) v5(36.47,8.45) v5(36.52,39.38) v5(36.49,28.99) v5(36.49,16.85) v5(36.67,43.68) v5(36.64,23.28) v5(36.9,49.87) v5(36.97,30.44) v5(37.13,52.03) v5(37.25,53.48) v5(37.28,29.02) v5(37.38,51.3) v5(37.46,29.81) v5(37.46,24.07) v5(37.41,10.88) v5(37.48,54.83) v5(37.53,50.43) v5(37.51,30.34) v5(37.48,2.65) v5(37.61,55.44) v5(37.63,54.14) v5(37.71,31.36) v5(37.71,24.83) v5(37.79,53.53) v5(37.81,52.79) v5(37.96,44.01) v5(38.12,55.66) v5(38.09,54.78) v5(38.14,54.01) v5(38.17,53.18) v5(38.24,4.61) v5(38.29,40.07) v5(38.37,51.45) v5(38.5,26.63) v5(38.65,40.75) v5(38.78,55.66) v5(38.8,53.91) v5(38.88,50.74) v5(38.98,56.15) v5(38.98,52.59) v5(39.21,49.9) v5(39.18,8.29) v5(39.18,2.68) v5(39.31,56.68) v5(39.39,61.68) v5(39.74,51.88) v5(39.87,57.37) v5(39.87,56.81) v5(40.12,49.9) v5(40.07,40.7) v5(40.23,51.12) v5(40.38,57.39) v5(40.5,21.48) v5(40.58,55.74) v5(40.73,56.12) v5(40.75,26.76) v5(40.78,56.91) v5(40.81,33.62) v5(40.96,40.73) v5(40.91,2.68) v5(41.06,49.9) v5(41.17,53.45) v5(41.37,63.01) v5(41.55,58.59) v5(41.52,47.69) v5(41.55,45.38) v5(41.5,34.2) v5(41.6,24.19) v5(41.72,37.86) v5(41.83,40.07) v5(42.18,29.27) v5(42.66,30.09) v5(42.69,47.66) v5(42.74,45.35) v5(42.77,29.5) v5(42.77,28.97) v5(43.43,31.26) v5(43.37,30.21) v5(43.6,33.24) v5(43.68,32.58) v5(43.91,35.67) v5(43.93,34.2) v5(43.91,29.53) v5(44.06,31.92) v5(43.98,30.42) v5(44.19,37.5) v5(44.24,34.84) v5(44.37,11.7) v5(44.39,33.21) v5(44.39,12.74) v5(44.54,18.5) v5(44.54,17.72) v5(44.62,36.31) v5(44.62,35.83) v5(44.77,38.16) v5(45.2,36.44) v5(45.43,18.5) v5(45.46,17.72) v5(47.31,15.56) v5(47.87,14.82) v5(48.25,15.43) v5(48.33,12.31) v5(48.71,32.4) v5(48.86,9.87) v5(48.91,11.01) v5(48.94,10.4) v5(49.17,31.2) v5(49.37,12.94) v5(49.55,11.49) v5(49.55,10.17) v5(49.95,15.2) v5(50.03,12.46) v5(50,9.69) v5(50.11,32.78) v5(50.23,13.78) v5(50.51,30.13) v5(50.72,35.88) v5(50.74,11.7) v5(50.77,10.02) v5(51.2,13.42) v5(51.38,12.43) v5(51.5,50.66) v5(51.68,15.58) v5(51.73,14.52) v5(51.78,30.72) v5(52.27,32.31) v5(52.44,56.05) v5(53.56,30.52) v5(53.59,28.99) v5(53.69,33.03) v5(54.09,28.41) v5(54.17,61.74) v5(54.47,35.17) v5(54.68,51.78) v5(54.8,57.24) v5(55.03,56.12) v7(0.73,9.54) v7(0.68,8.06) v7(0.73,6.79) v7(0.73,5.91) v7(1.8,55.74) v7(2.58,27.65) v7(5.33,60.01) v7(5.58,53.68) v7(6.14,4.94) v7(6.27,66.64) v7(6.29,65.82) v7(6.44,64.99) v7(6.62,59.22) v7(6.67,3.98) v7(6.82,63.59) v7(6.82,60.62) v7(6.8,54.9) v7(6.95,66.71) v7(6.9,61.68) v7(7.61,66.71) v7(7.66,65.27) v7(11.6,62.78) v7(11.62,61.74) v7(12.41,62.24) v7(18.86,43.27) v7(19.35,10.22) v7(28.29,3.7) v7(32.55,66.92) v7(33.44,66.94) v7(34.31,66.94) v7(35.09,66.94) v7(36.06,66.94) v7(36.26,0.67) v7(37.02,0.67) v7(37.23,66.97) v7(39.11,10.55) v7(42.08,1.79) v7(42.58,0.85) v7(42.87,66.94) v7(46.6,66.97) v7(47.92,13.83) v7(48.51,14.47) v7(49.01,15) v7(51.12,31.8) v7(51.25,32.6) v8(8.34,9.42) v8(11.4,46.88) v8(12.44,46.88) v8(13.83,22.47) v8(17.11,49.37) v8(18.05,48.48)
SODIMM_VIN5A_CLK0/VIN2B_HSYNC1: length 59.2
  TOP w0.12: v8(38.27,35.97) U6.AC5
  INT_L3 w0.091: v3(44.01,45.86) 44.01,46.62 45.22,47.83 52.23,47.83 53.43,46.62 54.12,46.62 55.8,44.95 55.8,36.41 56,36.21 56,35.37 53.94,33.31 53.94,30.21 54.23,29.93 54.41,29.93 54.65,29.69 54.65,29.43 55.35,28.73 55.35,18.07 55.37,17.96 56.71,16.62 v2(57.62,16.62)
  SIG_L5 w0.091: v3(44.01,45.86) 43.93,45.78 43.93,42.56 41.75,40.37 40.48,40.37 40.05,39.94 40.05,39.51 38.64,38.11 38.64,36.51 38.27,36.13 v8(38.27,35.97)
SODIMM_VIN5A_D0/VIN2B_D0: length 34.6
  TOP w0.114: U6.AD6 v2(37.5,35.94) ; XP1.163 v1(58.04,53.18)
  GND_L2 w0.091: v1(58.04,53.18) v2(57.65,53.18)
  INT_L3 w0.091: v3(43.81,48.3) 43.88,48.37 43.88,51.63 44.82,52.57 47.18,52.57 47.64,53.02 57.49,53.02 v2(57.65,53.18) ; v2(37.5,35.94) 37.94,36.39 38.47,36.39 38.64,36.56 38.64,36.96 v3(39.16,37.48)
  SIG_L10 w0.091: v3(39.16,37.48) 39.16,38.29 40.26,39.39 40.26,40.4 43.22,43.37 43.22,47.71 v3(43.81,48.3)
SODIMM_VIN5A_D1/VIN2B_D1: length 42.2
  TOP w0.114: U6.AC8 v2(35.86,35.95)
  INT_L3 w0.091: v2(35.86,35.95) v3(35.86,36.51)
  SIG_L5 w0.091: v3(54.75,63.59) 54.32,63.59 52.06,61.33 52.06,54.85 49.14,51.93 48.23,51.93 46.28,49.98 45.93,49.98 44.94,49 44.94,47.78 43.36,46.2 43.36,42.98 41.43,41.04 40.03,41.04 35.86,36.87 v3(35.86,36.51)
  SIG_L10 w0.091: v5(57.12,64.58) 57.07,64.58 55.97,63.49 54.86,63.49 v3(54.75,63.59)
  BOTTOM w0.114: v5(57.12,64.58) XP1.202
SODIMM_VIN5A_D2/VIN2B_D2: length 51.7
  TOP w0.114: v8(39.9,35.95) 39.85,35.95
  TOP w0.12: 39.85,35.95 U6.AC3
  SIG_L8 w0.091: v8(39.9,35.95) 39.85,35.95 U6.AC3 38.02,35.57 37.86,35.42 37.86,34.13 38.22,33.77 38.22,32.63 37.81,32.22 37.81,30.95 38.77,29.99 40.29,29.99 40.56,29.73 40.56,29.09 41.26,28.39 41.26,24.76 42.42,23.59 42.99,23.59 43.17,23.59 43.53,23.59 44.79,22.34 44.79,13.76 47.59,10.96 51.83,10.96 51.96,10.83 52.58,10.21 54.97,10.21 57.42,12.67 57.42,17.06 56.84,17.64 v3(56.81,17.64)
  SIG_L10 w0.091: v5(57.12,17.21) 56.81,17.51 v3(56.81,17.64)
  BOTTOM w0.114: XP1.52 57.15,17.18 v5(57.12,17.21)
SODIMM_VIN5A_D3/VIN2B_D3: length 55
  TOP w0.114: U6.AC9 v2(35.07,35.93)
  INT_L3 w0.091: v3(39.56,29.43) 39.57,29.43 39.64,29.5 39.64,30.49 39.36,30.77 38.45,30.77 37.84,30.16 35.55,30.16 34.66,31.05 34.66,32.14 33.85,32.96 33.85,35.32 34.08,35.55 34.69,35.55 v2(35.07,35.93)
  SIG_L8 w0.091: v3(39.56,29.43) 39.56,29.43 39.56,29.27 41.04,27.8 41.04,24.67 42.33,23.38 43.08,23.38 43.26,23.38 43.44,23.38 44.57,22.25 44.57,13.67 47.5,10.74 51.74,10.74 52.49,9.99 55.06,9.99 57.8,12.73 57.8,18.46 57.27,18.99 v3(57.12,18.99)
  SIG_L10 w0.091: v5(57.68,18.99) v3(57.12,18.99)
SODIMM_VIN5A_D4/VIN2B_D4: length 56.8
  TOP w0.114: v2(37.41,35.27) 37.39,35.27 37.38,35.28 37.36,35.28 U6.AC6
  INT_L3 w0.091: v2(37.41,35.27) 37.41,35.22 36.14,33.95 35.1,33.95 v3(34.89,33.74) ; v2(57.7,21.37) v3(58.11,21.37)
  SIG_L8 w0.091: v3(58.11,21.37) 58.56,21.37 59.01,20.93 59.01,12.4 55.51,8.9 47.8,8.9 43.28,13.42 43.28,16.56 43.26,16.58 43.26,16.69 41.75,18.2 41.69,18.2 41.31,18.2 39.22,20.29 39.22,21.29 38.68,21.84 38.68,27.37 38.11,27.94 38.11,28.28 36.82,29.57 36.82,30.2 36.39,30.62 36.39,31.2 35.15,32.45 35.15,33.52 34.93,33.74 v3(34.89,33.74)
SODIMM_VIN5A_D5/VIN2B_D5: length 54.8
  TOP w0.114: U6.AC7 v2(36.69,35.95)
  INT_L3 w0.091: v3(35.96,34.53) 36.29,34.86 36.29,35.55 v2(36.69,35.95) ; v2(57.98,20.74) v3(58.41,20.74)
  SIG_L8 w0.091: v3(58.41,20.74) 58.79,20.36 58.79,12.49 55.42,9.12 47.89,9.12 43.5,13.51 43.5,16.68 43.48,16.7 43.48,16.8 41.86,18.42 41.4,18.42 39.46,20.36 39.46,24.47 40.17,25.18 40.17,26.66 39.23,27.6 38.91,27.6 38.89,27.62 38.85,27.62 38.33,28.15 38.33,28.37 37.04,29.66 37.04,30.29 36.61,30.71 36.61,31.41 36.26,31.76 36.26,34.23 v3(35.96,34.53)
SODIMM_VIN5A_D6/VIN2B_D6: length 58.2
  TOP w0.12: U6.AC4 v8(39.07,35.97)
  INT_L3 w0.091: v3(58.28,22.57) v2(57.8,22.57)
  SIG_L8 w0.091: v3(58.28,22.57) 58.26,22.59 56.99,22.59 56.33,21.93 56.33,20.41 58.02,18.72 58.02,12.64 55.15,9.77 48.16,9.77 44.36,13.58 44.36,22.15 43.35,23.16 42.99,23.16 42.88,23.16 42.24,23.16 40.82,24.58 40.82,27.43 40.34,27.92 38.65,29.61 38.65,29.78 37.59,30.84 37.59,32.31 37.86,32.58 37.86,33.75 37.64,33.97 37.33,33.97 37.05,34.25 37.05,34.56 37.53,35.04 37.53,35.95 37.93,36.35 38.69,36.35 v8(39.07,35.97)
SODIMM_VIN5A_D7/VIN2B_D7: length 66.4
  TOP w0.114: v2(56.58,21.81) 55.11,23.28 55.11,25.51 56.37,26.78 XP1.75
  TOP w0.12: v8(39.07,36.77) U6.AD4
  INT_L3 w0.091: v2(56.58,21.81) 56.76,21.81 v3(57.04,21.53)
  SIG_L8 w0.091: v8(39.07,36.77) 39.07,36.88 38.24,37.71 37.66,37.71 37.43,37.48 37.43,36.34 37.3,36.21 37.3,35.12 36.83,34.65 36.83,34.64 36.8,34.61 36.8,34.07 37.05,33.82 37.05,30.9 37.56,30.39 37.56,29.76 38.22,29.1 38.85,29.1 40.61,27.34 40.61,24.49 42.15,22.94 42.97,22.94 43.08,22.94 43.26,22.94 44.14,22.06 44.14,13.49 48.07,9.56 55.24,9.56 58.23,12.55 58.23,19.29 57.7,19.83 57.7,20.87 v3(57.04,21.53)
SODIMM_VIN5A_DE0/VIN2B_VSYNC1: length 42.5
  TOP w0.12: v8(39.07,35.17) U6.AB4
  INT_L3 w0.091: v2(57.62,14.85) 56.79,14.01 v3(56.79,13.73)
  SIG_L8 w0.091: v3(56.79,13.73) 56.86,13.65 56.86,12.42 55.08,10.63 52.7,10.63 52.09,11.24 47.72,11.24 45.01,13.95 45.01,22.43 44.95,22.49 44.95,22.52 43.65,23.81 43.62,23.81 42.61,23.81 41.48,24.95 41.48,28.48 40.77,29.18 40.77,29.82 39.82,30.77 38.88,30.77 38.65,31 38.65,34.75 38.84,34.94 38.84,34.94 v8(39.07,35.17)
SODIMM_VIN5A_HSYNC0/VIN2B_DE1: length 40.3
  TOP w0.12: v8(35.87,35.17) U6.AB8
  SIG_L5 w0.091: v3(53.15,61.76) 52.37,60.97 52.37,54.84 49.04,51.52 48.44,51.52 46.69,49.77 46.02,49.77 45.16,48.9 45.16,47.69 43.58,46.11 43.58,42.72 41.57,40.7 40.45,40.7 37.08,37.33 37.08,36.39 35.87,35.18 v8(35.87,35.17)
  SIG_L10 w0.091: v3(53.15,61.76) 53.2,61.81 56.38,61.81 56.74,62.17 v5(57.6,62.17)
SODIMM_VIN5A_VSYNC0/VIN2B_CLK1: length 35.6
  TOP w0.114: v2(57.04,57.98) XP1.179
  TOP w0.12: v8(38.27,35.17) U6.AB5
  INT_L3 w0.091: v2(57.04,57.98) 55.85,57.98 v3(54.6,56.73)
  SIG_L5 w0.091: v8(38.27,35.17) 38.48,35.17 38.86,35.55 39.36,35.55 39.52,35.71 39.52,36.11 39.74,36.33 39.74,36.82 40.68,37.76 41.89,37.76 44.54,40.41 44.54,45.3 45.91,46.67 45.91,48.86 46.39,49.33 48.17,49.33 49.67,50.84 49.67,51.58 54.55,56.45 54.55,56.68 v3(54.6,56.73)
VDD_1V8: length 54.5
  TOP w0.254: U6.M9 35.01,27.12 35.03,27.12 v8(35.08,27.17) U6.M8 v8(35.87,27.17) U6.N8 v8(35.87,27.97) U6.P8 ; U6.Y21 v8(24.67,32.77) U6.W21 v8(24.67,31.97) ; v8(24.67,31.97) U6.V22 ; v8(24.67,31.97) U6.V21 ; U6.R8 v8(35.08,29.57) 35.08,29.57 35.08,29.58 U6.T8 ; v8(25.47,27.97) U6.P21 v8(24.67,27.97) U6.N21 v8(25.47,27.97) ; v8(25.47,27.97) U6.P20 ; U6.AA18 v8(27.07,34.37) U6.AA19 ; U6.J21 v8(24.67,23.97) U6.J22 ; U6.H17 v8(27.87,23.17) U6.G18 ; U6.Y7 v8(36.67,33.57) U6.AA7 ; U6.W18 v8(27.87,32.77) U6.W17
  TOP w0.381: U3.B6 v7(35.12,55.84) ; v7(48.63,50.51) 48.56,50.43 TP20.1
  INT_L3 w0.381: 46.58,57.26 46.37,57.06 45.53,57.06 45.08,56.6 42.69,56.6 42.31,56.99 35.83,56.99 35.12,56.27 v7(35.12,55.84) ; 46.58,57.26 46.58,58.59 v3(47.64,59.65) ; 46.58,57.26 v7(46.58,56.55)
  PWR_L6 w0.381: 37.25,55.49 38.59,55.49
  SIG_L10 w0.381: v3(47.64,59.65) v5(47.02,59.65) ; v5(38.4,37.61) 38.09,37.3 v3(38.02,37.3)
  BOTTOM w0.114: v8(35.08,29.57) 35.01,29.63 C290.1 ; C293.1 27.91,23.21 v8(27.87,23.17) ; v8(25.47,27.97) 25.54,28.05 C285.1
  BOTTOM w0.254: v8(27.07,34.37) 26.97,34.28 C289.1 ; C287.1 27.26,32.17 v8(27.87,32.77) ; C295.1 36.67,34.01 v8(36.67,33.57)
  BOTTOM w0.381: D2.3 46.42,56.24 ; 46.42,56.24 46.58,56.39 v7(46.58,56.55) ; 46.42,56.24 48.4,56.24 Q1.3 ; v7(35.12,55.84) 35.53,55.44 C41.2 ; v7(48.63,50.51) 47.9,49.78 Q2.3 47.52,49.88 D3.3 43.86,49.97 43.86,52.9 44.57,53.61 R17.1 ; R16.1 v5(47.02,59.65)
VDD_3V3: length 278
  TOP w0.203: R156.1 15.81,4.53 16.64,5.35 C54.1 17.86,5.35 U5.5 18.55,5 19.22,4.33 19.22,2.93 v2(19.47,2.68) 19.52,2.73 R54.1 ; R167.1 R154.1 11.08,4.87 11.32,5.12 12.41,5.12 12.93,4.6 R155.1
  TOP w0.254: v8(31.87,31.17) U6.V12 ; U6.H18 v8(27.07,23.17) U6.H19 ; U6.N5 v8(38.27,27.17) U6.N4 39.05,27.19 v8(39.11,27.19) ; v8(39.07,32.77) U6.W4 38.27,32.77 U6.W5 ; U6.AB6 v8(36.67,35.17) U6.AB7 ; 38.27,30.37 38.4,30.24 38.48,30.32 38.48,30.32 38.86,30.32 38.91,30.37 v8(39.07,30.37) U6.T4 38.27,30.37 ; 38.27,30.37 U6.T5 ; R148.1 R145.1 R144.1 ; v8(37.49,21.58) 37.51,21.55 37.51,21.53 U6.E5 ; R151.1 35.91,9.68 35.91,9.56 36.16,9.31 36.94,9.31 37.19,9.06 C153.1 ; U6.E22 v8(23.87,20.77) U6.D22 v8(23.87,19.97) ; v8(23.87,19.2) 23.87,19.17 U6.B23 ; v8(29.47,23.17) U6.H15 ; v8(29.47,23.17) U6.H16 ; v8(29.47,23.17) U6.G15 v8(29.47,22.37) ; U6.AD7 v8(36.67,36.77) U6.AE7 ; v8(34.27,31.17) U6.U10 ; v8(35.86,29.58) U6.R7 ; U6.AD5 v8(38.27,36.77) 38.32,36.82 38.32,36.98 38.32,36.99 38.32,37.36 38.32,37.36 38.32,37.66 38.07,37.91 37.93,37.91 U6.AF5 ; v8(28.67,19.97) U6.D16 v8(28.67,20.77) U6.E16 ; v2(42.3,22.94) 42.66,22.57 42.66,21.37 43.11,20.92 R194.1 43.24,20.94 43.98,20.94 ; R218.1 R205.1 R203.1 R201.1 R199.1 R197.1 R185.1 49.23,20.79 R67.1 ; v7(45.44,20.6) 45.1,20.94 43.98,20.94 ; 43.98,20.94 43.98,21.2 v2(43.9,21.29) ; U6.P10 34.21,28.72 34.21,28.72 v8(34.27,28.78) U6.R10 ; R304.1 v2(52.77,21.96) 53.39,21.96 C216.1 53.51,21.89 U20.5 ; v8(39.08,22.39) 39.05,22.39 U6.G4 v8(38.27,22.37) U6.G5 ; U6.E10 v8(34.27,20.77) U6.D10 ; v8(37.47,18.37) U6.B6 ; U6.K8 v8(35.87,24.77) U6.J8 35.47,24.35 35.85,23.97 v8(35.87,23.97) U6.H8 v8(35.07,23.17) U6.H9 v8(34.27,23.17) U6.H10 v8(33.47,23.17) U6.H11 ; v8(22.27,19.17) U6.C24 ; v8(39.88,21.58) U6.E3
  TOP w0.381: R148.1 R150.1 R147.1 R149.1 R146.1 35.76,9.83 R151.1 ; R33.1 46.29,48.29 v1(47.46,49.47) ; U2.10 11.41,64.04 v7(10.61,64.83) 10.61,65.56 C2.1 10.52,65.79 10.99,66.26 11.78,66.26 R11.1 R13.2 ; 17.85,56.93 17,56.93 TP23.1 ; 17.85,56.93 v7(17.72,57.06) ; 17.85,56.93 L9.2 ; U14.1 37.24,8.62 C153.1 ; R55.2 19.58,9.26 v7(20.29,9.26) 20.68,9.26 R57.2 24.2,12.37 24.2,14.29 24.54,14.63 R56.2 ; v7(32.76,53.43) 32.76,53.44 U3.D9 ; U18.5 53.46,42.59 53.08,42.21 v7(53.08,41.9) 52.95,41.9 52.26,41.21 52.26,40.2 51.66,39.59 50.11,39.59 49.72,39.97 49.72,41.21 R275.1 ; v2(27.46,7.31) 27.47,7.31 27.47,7.23 U12.J10 ; v2(48.76,19.9) 48.85,20 R185.1
  GND_L2 w0.381: v1(47.46,49.47) v2(47.73,49.74)
  INT_L3 w0.203: v2(15.82,4.51) 15.37,4.96 13.19,4.96 12.95,4.71 v2(12.95,4.53)
  INT_L3 w0.254: v2(19.47,2.68) 19.98,2.68 20.41,3.11 22.19,3.11 v7(22.45,3.37) ; v2(36.8,3.47) 37,3.47 37.56,4.03 v7(38.55,4.03) ; v2(45.91,27.72) 46.45,27.72 47.64,26.53 47.64,25.92 48.2,25.36 v2(48.81,25.36) ; v3(40.71,23.05) 42.18,23.05 v2(42.3,22.94) ; v2(43.9,21.29) 43.9,21.31 43.91,21.33 43.91,21.4 44.62,22.11 v2(44.62,22.16)
  INT_L3 w0.381: v3(25.87,8.95) 25.37,8.95 25.04,9.29 v2(25.04,9.41) ; v3(28.21,8.57) 28.57,8.93 v2(29.53,8.93) v2(30.55,8.93) 30.19,9.28 v3(30.19,9.44) ; v3(51.25,20.38) 52.34,20.38 52.77,20.82 v2(52.77,21.5) v2(52.77,21.96) ; v2(44.95,57.8) 44.82,57.67 v3(44.39,57.67) ; v3(36.54,7.89) 36.54,8.01 v2(37.28,8.75) ; v7(17.72,56.43) 18.58,55.56 26.59,55.56 27.09,55.05 28.69,55.05 29.1,54.65 v2(29.15,54.65) ; v2(22.34,61.28) 22.39,61.33 22.39,61.99 19.3,65.09 16.27,65.09 14.7,63.51 ; v2(25.54,9.92) 25.05,9.92 v3(25.04,9.91) ; v3(51.55,51.04) 50.25,49.74 v2(47.73,49.74) ; v7(45.44,20.6) 45.51,20.54 48.12,20.54 v2(48.76,19.9)
  SIG_L10 w0.254: v3(40.71,23.05) 40.48,23.05 39.8,22.37 39.1,22.37 v8(39.08,22.39) ; v5(44.01,13.81) 43.93,13.88 39.84,13.88 v5(39.15,13.18)
  SIG_L10 w0.381: P1.5 15.32,3.08 15.61,3.37 v7(22.45,3.37) ; v5(27.73,8.85) 28.01,8.57 v3(28.21,8.57) ; v3(36.54,7.89) 37.11,7.89 v5(37.18,7.96) ; v3(51.25,20.38) v5(51.25,19.88) ; v3(51.55,51.04) 51.55,51.47 v5(51.58,51.5) ; v5(30.85,8.57) 30.85,8.78 v3(30.19,9.44) ; v5(25.77,10.22) 25.35,10.22 v3(25.04,9.91) ; v3(45.56,35.95) 45.43,35.83 45.43,35.4 v5(45.41,35.37)
  BOTTOM w0.114: C311.1 36.06,24.17 v8(35.87,23.97) ; C310.1 23.66,19 v8(23.87,19.2) ; v8(37.47,18.37) 37.4,18.3 C154.1 ; C61.1 35.17,23.28 v8(35.07,23.17) ; 42,27.52 v8(41.95,27.52)
  BOTTOM w0.127: R195.2 38.17,6.5 38.66,6.01 38.76,6.01 39.11,5.66 R51.2
  BOTTOM w0.203: R220.1 40.78,27.57 41.9,27.57 v8(41.95,27.52) 41.93,27.5 41.93,25.83 42.41,25.35 42.41,25.07 42.11,24.77 41.56,24.77 41.28,25.04 R207.1 ; 23.27,3.53 22.78,3.04 22.78,2.34 23.3,1.82 ; C147.2 28.67,19.82 v8(28.67,19.97) ; C159.1 34.54,1.54 34.54,1.61 34.6,1.67 34.63,1.67 34.75,1.79 34.93,1.79 35.22,2.08 R230.2 ; C62.1 21.49,7.43 20.54,8.38 R66.2 ; 23.3,1.82 R226.2 ; 23.3,1.82 21.68,1.82 R65.1 ; v8(29.47,22.37) 29.47,22.67 C314.1 29.47,22.82 v8(29.47,23.17) ; R232.2 22.77,4.12 22.77,5.16 22.91,5.31 R235.2 ; R245.1 R244.1 24.54,17.72 23.94,18.33 C310.1 ; C196.1 27.18,23.06 v8(27.07,23.17)
  BOTTOM w0.254: C308.1 38.6,30.43 38.6,30.37 ; R246.2 35.9,5.2 37,4.1 37,4.1 37.18,3.92 38.45,3.92 v7(38.55,4.03) ; R224.1 38.34,28.91 38.74,29.31 38.74,29.38 38.74,29.38 38.74,29.77 38.6,29.91 38.6,30.37 ; C312.1 36.87,35.37 v8(36.67,35.17) 36.2,34.71 35.67,34.71 35.63,34.75 R53.1 ; C312.1 37.25,35.75 v8(38.27,36.77) ; C312.1 36.87,36.13 36.67,36.33 v8(36.67,36.77) ; 33.31,13.25 33.62,13.25 33.97,12.89 33.97,12.02 v7(33.95,12) ; 33.31,13.25 33.31,13.65 33.67,14.01 35.02,14.01 36.77,12.26 37.55,12.26 37.98,12.69 R142.1 R143.1 ; 33.31,13.25 R153.2 ; v8(39.08,22.39) 39.12,22.42 39.82,22.42 C315.1 ; v8(31.87,31.17) 31.8,31.1 C150.2 ; v8(37.49,21.58) 37.51,21.55 37.51,21.45 37.88,21.07 C316.1 39.37,21.07 v8(39.88,21.58) ; 38.6,30.37 v8(39.07,30.37) ; R182.1 41.76,23.23 42.23,23.7 42.23,24.47 41.96,24.74 41.56,24.74 R207.1 ; C307.1 39.8,32.78 39.61,32.78 39.61,32.77 v8(39.07,32.77) ; C309.1 34.33,28.84 v8(34.27,28.78) ; v8(23.87,19.97) 24.27,20.37 24.27,20.46
  BOTTOM w0.381: v5(30.85,8.57) 30.77,8.49 C142.2 ; 39.11,4.71 40.17,4.71 40.55,4.33 U15.8 ; 39.11,4.71 R51.2 ; 39.11,4.71 C157.2 39.1,4.5 38.63,4.03 v7(38.55,4.03) ; C62.1 21.63,7.37 ; R232.2 22.61,3.53 v7(22.45,3.37) ; L10.2 54.4,35.83 v7(54.45,35.78) ; v5(45.41,35.37) 45.41,34.89 L12.2 ; v5(27.25,7.48) 27.71,7.94 C141.2 27.83,7.89 C140.2 ; U13.2 33.97,11.98 v7(33.95,12) ; L18.2 46.25,8.78 45.13,7.66 45.13,6.29 v7(46.17,5.25) ; 50.61,51.73 50.84,51.96 50.84,54.69 51.22,55.07 52.22,55.07 52.57,54.73 R327.2 53.58,53.35 R323.2 ; 50.61,51.73 51.52,51.73 R216.1 ; 50.61,51.73 50.19,51.31 50.19,50.82 51.01,50 53.94,50 54.54,50.6 R212.1 ; C53.1 32.76,53.74 v7(32.76,53.43) ; R246.2 R247.2 ; U16.8 34.17,1.37 C159.1 v7(34.27,0.79) ; R5.2 R1.2 49.78,59.6 49.52,59.34 Q1.2 49.52,58.13 49.12,57.72 v7(48.43,57.72) ; 44.67,39.36 43.93,39.36 43.25,38.68 v8(43.25,37.96) ; v5(27.73,8.85) 27.84,8.96 C143.2 ; v5(51.25,19.88) 50.18,19.88 L16.2 49.19,20.51 49.19,20.6 v7(45.44,20.6) 43.3,18.46 L17.2 ; R170.1 v5(37.18,7.96) ; C158.1 42,27.52 ; v7(20.29,9.26) 20.29,8.4 R66.2
  vias: v1(25.04,10.4) v1(26.03,9.92) v1(27.04,7.4) v1(29.05,9.41) v2(25.04,10.4) v2(26.03,9.92) v2(27.04,7.4) v2(29.05,9.41) v3(27.04,6.91) v3(50.89,49.64) v3(51.48,49.64) v3(52.06,49.64) v3(52.65,49.64) v3(53.28,49.77) v4(24.35,10.17) v4(24.35,9.21) v4(27.7,6.72) v5(23.82,10.33) v5(23.82,9.11) v5(27.7,6.72) v7(9.92,64.68) v7(9.92,64.17) v7(16.58,57.77) v7(16.63,56.2) v7(17.19,57.82) v7(17.21,56.17) v7(17.75,57.62)
VDD_CORE: length 41
  TOP w0.254: v8(31.87,27.97) U6.N13 ; v8(31.87,27.97) U6.P12 v8(32.67,27.97) U6.P11 v8(33.47,27.97) U6.N10 ; v8(31.87,27.97) U6.P13 ; U6.V16 v8(28.67,31.17) U6.U16 v8(28.67,30.37) U6.T16 v8(28.67,29.57) U6.R16 ; U6.L7 v8(35.87,25.57) U6.L8 ; U6.U9 v8(35.07,31.17) ; v8(35.07,31.17) U6.U8 v8(35.87,31.17) U6.V8 v8(35.07,31.17) ; U6.H13 v8(31.07,23.17) U6.H14 ; U6.J17 v8(27.87,23.97) U6.J18 ; U6.T19 v8(26.27,29.57) U6.R19 ; U6.T13 v8(31.87,30.37) U6.U13 ; U6.R11 33.09,29.17 v8(33.49,28.77)
  TOP w0.381: L7.2 42.07,64.36 C30.1 ; C30.1 42.26,62.88 TP14.1 ; C30.1 43.12,63.31 v7(43.32,63.31) ; U3.B1 v2(35.16,60.68)
  INT_L3 w0.381: v7(43.32,63.31) 37.79,63.31 v2(35.16,60.68)
  SIG_L10 w0.381: v7(31.12,19.95) 30.88,19.71 v5(30.88,19.37) ; v5(33.82,16.4) v3(33.82,15.91)
  BOTTOM w0.114: v8(28.67,30.37) 28.75,30.46 C229.1 ; v8(28.67,29.57) 28.75,29.66 C225.1 ; C218.1 26.38,29.46 v8(26.27,29.57)
  BOTTOM w0.254: 33.06,28.29 32.99,28.29 v8(32.67,27.97) ; v8(31.87,27.97) 32.2,28.3 C219.1 ; C224.1 27.72,24.12 v8(27.87,23.97)
  BOTTOM w0.381: C228.1 43.1,63.08 v7(43.32,63.31)
  vias: v7(41.14,63.84) v7(43.35,65.11) v7(43.35,63.92)
VDD_DSP: length 49.4
  TOP w0.254: v8(32.67,26.37) U6.M12 31.87,26.37 ; v8(32.67,26.37) U6.M11 v8(33.47,26.37) ; v8(32.67,26.37) U6.L12 ; v8(32.67,26.37) U6.L11 ; 31.87,26.37 U6.L12 ; 31.87,26.37 U6.M13 ; U6.K10 34.27,25.57 U6.L10 ; U6.K10 v8(33.47,24.77) U6.K11 ; U6.K10 v8(33.47,25.57) ; U6.K12 v8(31.87,24.77) ; U6.K12 v8(32.67,25.57) ; U6.K12 32.67,24.77 U6.K11 ; v8(31.87,24.77) U6.J13 ; v8(31.87,24.77) U6.K13 ; U6.K11 v8(33.47,25.57) ; U6.K11 v8(32.67,25.57) ; v8(33.47,25.57) U6.L10 ; v8(33.47,25.57) U6.L11 ; U6.L12 v8(32.67,25.57) ; U6.L11 v8(33.47,26.37) ; U6.L11 v8(32.67,25.57) ; v8(33.47,26.37) U6.M10 34.27,26.37 U6.L10 ; v8(33.47,26.37) U6.L10
  TOP w0.381: C26.1 24.19,65.85 25.62,64.42 L4.2 ; C26.1 23.41,66.18 TP11.1 v7(21.43,66.15) ; C26.1 23.35,65.47 v7(21.96,65.47) ; v7(18.66,66.41) 18.64,66.43 C237.1 ; C234.1 18.51,65.65 v7(18.66,65.8) ; U3.K2 v2(28.01,59.09)
  INT_L3 w0.381: v2(28.01,59.09) 28.01,61.56 24.83,64.73 22.17,64.73 v7(21.99,64.91)
  PWR_L6 w0.381: v7(18.66,65.8) 18.86,65.6 21.84,65.6 v7(21.96,65.47)
  BOTTOM w0.381: C240.1 18.25,66.05 ; 18.25,66.05 18.35,66.05 18.47,65.94 18.52,65.94 v7(18.66,65.8) ; 18.25,66.05 18.61,66.41 v7(18.66,66.41) ; L4.2 26,65.56 C28.1
  vias: v7(21.43,65.62) v7(21.45,65.09) v7(22.04,66.15)
